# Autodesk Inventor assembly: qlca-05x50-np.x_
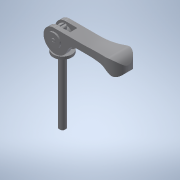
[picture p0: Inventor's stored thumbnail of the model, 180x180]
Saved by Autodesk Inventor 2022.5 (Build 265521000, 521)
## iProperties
Part Number: qlca-05x50-np.x_
Material: 一般
Document SubType Name: Assembly
Designer: ImaoCorp
Sending System: SOLIDWORKS 2017-2017317
MC: AMD64
MC_MODEL: Intel64 Family 6 Model 60 Stepping 3, GenuineIntel
OS: Windows_NT
FRU: Parasolid Version 29.0, build 201,  4-17-2017
FORMAT: text
GUISE: transmit
KEY: qlca-05x50-np
FILE: qlca-05x50-np.x_t
DATE: Wed Sep 04 15:48:17 2019
Author: ImaoCorp
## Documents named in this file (4)
- X:\14_SW2022-Inv2022\00_全2023-1023新製品(TCC)まで\q\qlca-05x50-np\QLCA-05X50-NP.iam
- X:\14_SW2022-Inv2022\00_全2023-1023新製品(TCC)まで\q\qlca-05x50-np\qlca-05x50-np_01.ipt
- X:\14_SW2022-Inv2022\00_全2023-1023新製品(TCC)まで\q\qlca-05x50-np\qlca-05x50-np_02.ipt
- X:\14_SW2022-Inv2022\00_全2023-1023新製品(TCC)まで\q\qlca-05x50-np\qlca-05x50-np_03.ipt
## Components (3 placed, 3 different names)
1. qlca-05x50-np_01
2. qlca-05x50-np_02
3. qlca-05x50-np_03
